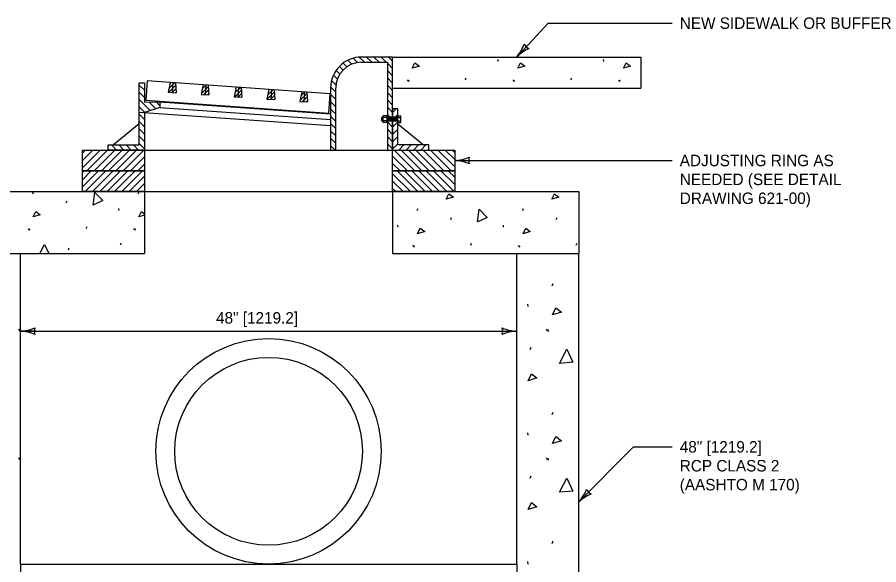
# Model space of a CAD drawing. Extents: x 49991.4 to 50057, y 49987.6 to 50011.4.
# Drawn here: x 50001.401 to 50005.915, y 49990.219 to 49993.085 of the extents above; entities that cross this region are included whole.
import ezdxf

# ---------------------------------------------------------------- set-up
doc = ezdxf.new("R2010")
doc.units = 0
for name, color, linetype in [('Level 1', 7, 'Continuous'), ('Level 2', 7, 'Continuous'), ('Level 3', 7, 'Continuous'), ('Level 4', 7, 'Continuous')]:
    doc.layers.add(name, color=color, linetype=linetype)

msp = doc.modelspace()

# ---------------------------------------------------------------- linework, layer by layer
at = {"layer": 'Level 1'}
for p, q in [((50003.1932, 49992.8766), (50003.2199, 49992.85)), ((50003.2311, 49992.8771), (50003.2582, 49992.85)), ((50003.2694, 49992.8771), (50003.2965, 49992.85)), ((50003.3077, 49992.8771), (50003.3348, 49992.85)), ((50003.346, 49992.8771), (50003.3679, 49992.8552)), ((50003.3679, 49992.8771), (50004.6679, 49992.8771)), ((50004.6679, 49992.8771), (50004.6679, 49992.7146)), ((50003.0889, 49992.8278), (50003.108, 49992.8087)), ((50003.1093, 49992.8456), (50003.1288, 49992.8262)), ((50003.1331, 49992.8601), (50003.1536, 49992.8397)), ((50003.1607, 49992.8708), (50003.1834, 49992.8482)), ((50003.3408, 49992.844), (50003.3679, 49992.8169)), ((50003.9187, 49992.8632), (50003.9198, 49992.8528)), ((50004.4717, 49992.8632), (50004.4728, 49992.8528)), ((50003.0716, 49992.8068), (50003.0911, 49992.7872)), ((50003.3408, 49992.8057), (50003.3679, 49992.7786)), ((50002.203, 49992.7433), (50002.1927, 49992.6931)), ((50002.1969, 49992.7135), (50002.2252, 49992.7418)), ((50002.2018, 49992.7375), (50002.2073, 49992.743)), ((50002.2165, 49992.7424), (50002.213, 49992.6917)), ((50002.23, 49992.7414), (50002.2333, 49992.6903)), ((50003.0478, 49992.754), (50003.071, 49992.7308)), ((50003.0577, 49992.7824), (50003.0784, 49992.7616)), ((50003.3408, 49992.7674), (50003.3679, 49992.7403)), ((50003.4445, 49992.7583), (50003.4491, 49992.7513)), ((50003.4491, 49992.7556), (50003.4537, 49992.7487)), ((50003.7493, 49992.7583), (50003.7539, 49992.7687)), ((50003.9975, 49992.7583), (50004.0021, 49992.7513)), ((50004.0021, 49992.7556), (50004.0067, 49992.7487)), ((50004.3022, 49992.7583), (50004.3069, 49992.7687)), ((50004.5505, 49992.7583), (50004.5551, 49992.7513)), ((50004.5551, 49992.7556), (50004.5597, 49992.7487)), ((50002.0408, 49992.7305), (50002.0679, 49992.7034)), ((50002.0408, 49992.6922), (50002.0679, 49992.6651)), ((50002.1927, 49992.6931), (50002.2333, 49992.6903)), ((50002.1955, 49992.6929), (50002.2309, 49992.7283)), ((50002.2134, 49992.6917), (50002.232, 49992.7103)), ((50002.2313, 49992.6904), (50002.2331, 49992.6922)), ((50002.3753, 49992.7313), (50002.365, 49992.6811)), ((50002.3659, 49992.6856), (50002.4027, 49992.7225)), ((50002.3708, 49992.7097), (50002.3913, 49992.7302)), ((50002.3795, 49992.6801), (50002.4038, 49992.7044)), ((50002.3888, 49992.7303), (50002.3852, 49992.6797)), ((50002.4023, 49992.7294), (50002.4055, 49992.6783)), ((50002.5475, 49992.7192), (50002.5372, 49992.6691)), ((50002.5405, 49992.6688), (50002.5754, 49992.7037)), ((50002.5412, 49992.6887), (50002.5702, 49992.7177)), ((50002.5462, 49992.7128), (50002.5523, 49992.7189)), ((50002.561, 49992.7183), (50002.5575, 49992.6676)), ((50002.5745, 49992.7173), (50002.5777, 49992.6662)), ((50002.7197, 49992.7072), (50002.7094, 49992.657)), ((50002.7112, 49992.6569), (50002.7475, 49992.6932)), ((50002.7139, 49992.6787), (50002.7409, 49992.7057)), ((50002.7188, 49992.7028), (50002.723, 49992.707)), ((50002.7332, 49992.7062), (50002.7297, 49992.6556)), ((50002.7468, 49992.7053), (50002.75, 49992.6542)), ((50002.892, 49992.6951), (50002.8817, 49992.645)), ((50002.8875, 49992.6735), (50002.908, 49992.694)), ((50002.9055, 49992.6942), (50002.9019, 49992.6435)), ((50002.919, 49992.6933), (50002.9222, 49992.6421)), ((50003.043, 49992.7204), (50003.07, 49992.6935)), ((50003.3408, 49992.7291), (50003.3679, 49992.702)), ((50003.3679, 49992.7146), (50004.6679, 49992.7146)), ((50002.0408, 49992.6539), (50002.0985, 49992.5962)), ((50002.365, 49992.6811), (50002.4055, 49992.6783)), ((50002.3974, 49992.6788), (50002.405, 49992.6864)), ((50002.5372, 49992.6691), (50002.5777, 49992.6662)), ((50002.5584, 49992.6676), (50002.5765, 49992.6857)), ((50002.5763, 49992.6663), (50002.5776, 49992.6677)), ((50002.7094, 49992.657), (50002.75, 49992.6542)), ((50002.7291, 49992.6556), (50002.7486, 49992.6752)), ((50002.747, 49992.6544), (50002.7498, 49992.6572)), ((50002.8826, 49992.6494), (50002.9194, 49992.6863)), ((50002.8962, 49992.6439), (50002.9206, 49992.6683)), ((50002.9141, 49992.6427), (50002.9217, 49992.6502)), ((50003.0429, 49992.6823), (50003.07, 49992.6552)), ((50003.3408, 49992.6908), (50003.3679, 49992.6637)), ((50003.3408, 49992.6524), (50003.3679, 49992.6254)), ((50002.0408, 49992.6156), (50002.0698, 49992.5866)), ((50002.0925, 49992.6405), (50002.1273, 49992.6057)), ((50002.1301, 49992.6412), (50002.1492, 49992.6221)), ((50002.1492, 49992.6416), (50002.1492, 49992.6416)), ((50002.1492, 49992.6416), (50003.0429, 49992.5791)), ((50002.1492, 49992.613), (50003.0429, 49992.5505)), ((50002.2152, 49992.6083), (50002.2152, 49992.6083)), ((50002.8817, 49992.645), (50002.9222, 49992.6421)), ((50003.0429, 49992.644), (50003.07, 49992.6169)), ((50003.0429, 49992.6057), (50003.07, 49992.5786)), ((50003.3408, 49992.6141), (50003.3679, 49992.5871)), ((50003.3679, 49992.587), (50003.3872, 49992.6063)), ((50002.0408, 49992.5878), (50003.0429, 49992.5178)), ((50002.0408, 49992.5773), (50002.0679, 49992.5502)), ((50003.0429, 49992.5673), (50003.07, 49992.5403)), ((50003.31, 49992.5589), (50003.3134, 49992.5622)), ((50003.31, 49992.5589), (50003.31, 49992.5453)), ((50003.3117, 49992.5589), (50003.3117, 49992.5453)), ((50003.3134, 49992.5622), (50003.3134, 49992.5419)), ((50003.3168, 49992.5622), (50003.3134, 49992.5622)), ((50003.3151, 49992.5589), (50003.3151, 49992.5453)), ((50003.3168, 49992.5389), (50003.3168, 49992.5653)), ((50003.3168, 49992.5622), (50003.3168, 49992.5419)), ((50003.34, 49992.5697), (50003.3191, 49992.5697)), ((50003.34, 49992.5609), (50003.3191, 49992.5609)), ((50003.34, 49992.5345), (50003.34, 49992.5697)), ((50003.3408, 49992.5673), (50003.34, 49992.5673)), ((50003.3408, 49992.5758), (50003.3679, 49992.5488)), ((50003.3408, 49992.5369), (50003.3408, 49992.5673)), ((50003.395, 49992.5622), (50003.3408, 49992.5622)), ((50003.3422, 49992.5589), (50003.3422, 49992.5453)), ((50003.3438, 49992.5622), (50003.3438, 49992.5419)), ((50003.3455, 49992.5589), (50003.3455, 49992.5453)), ((50003.3472, 49992.5622), (50003.3472, 49992.5419)), ((50003.3489, 49992.5589), (50003.3489, 49992.5453)), ((50003.3506, 49992.5622), (50003.3506, 49992.5419)), ((50003.3523, 49992.5589), (50003.3523, 49992.5453)), ((50003.354, 49992.5622), (50003.354, 49992.5419)), ((50003.3557, 49992.5589), (50003.3557, 49992.5453)), ((50003.3574, 49992.5622), (50003.3574, 49992.5419)), ((50003.3591, 49992.5589), (50003.3591, 49992.5453)), ((50003.3608, 49992.5622), (50003.3608, 49992.5419)), ((50003.3625, 49992.5589), (50003.3625, 49992.5453)), ((50003.3642, 49992.5622), (50003.3642, 49992.5419)), ((50003.3658, 49992.5589), (50003.3658, 49992.5453)), ((50003.3675, 49992.5622), (50003.3675, 49992.5419)), ((50003.3679, 49992.5487), (50003.395, 49992.5758)), ((50003.3692, 49992.5589), (50003.3692, 49992.5453)), ((50003.3709, 49992.5622), (50003.3709, 49992.5419)), ((50003.3726, 49992.5589), (50003.3726, 49992.5453)), ((50003.3743, 49992.5622), (50003.3743, 49992.5419)), ((50003.376, 49992.5589), (50003.376, 49992.5453)), ((50003.3777, 49992.5622), (50003.3777, 49992.5419)), ((50003.3794, 49992.5589), (50003.3794, 49992.5453)), ((50003.3811, 49992.5622), (50003.3811, 49992.5419)), ((50003.3828, 49992.5589), (50003.3828, 49992.5453)), ((50003.3845, 49992.5622), (50003.3845, 49992.5419)), ((50003.3862, 49992.5589), (50003.3862, 49992.5453)), ((50003.3879, 49992.5622), (50003.3879, 49992.5419)), ((50003.3895, 49992.5589), (50003.3895, 49992.5453)), ((50003.3912, 49992.5622), (50003.3912, 49992.5419)), ((50003.3929, 49992.5589), (50003.3929, 49992.5453)), ((50003.395, 49992.5369), (50003.395, 49992.5673)), ((50003.395, 49992.5673), (50003.3958, 49992.5673)), ((50003.3958, 49992.5697), (50003.4086, 49992.5697)), ((50003.3958, 49992.5345), (50003.3958, 49992.5697)), ((50003.3958, 49992.5609), (50003.4086, 49992.5609)), ((50003.411, 49992.5389), (50003.411, 49992.5653)), ((50002.0408, 49992.5277), (50001.9054, 49992.4167)), ((50002.0408, 49992.539), (50002.0679, 49992.5119)), ((50003.0429, 49992.529), (50003.07, 49992.502)), ((50003.31, 49992.5453), (50003.3134, 49992.5419)), ((50003.3168, 49992.5419), (50003.3134, 49992.5419)), ((50003.34, 49992.5433), (50003.3191, 49992.5433)), ((50003.34, 49992.5345), (50003.3191, 49992.5345)), ((50003.3408, 49992.5369), (50003.34, 49992.5369)), ((50003.395, 49992.5419), (50003.3408, 49992.5419)), ((50003.3408, 49992.5375), (50003.3679, 49992.5105)), ((50003.3679, 49992.5104), (50003.395, 49992.5375)), ((50003.395, 49992.5369), (50003.3958, 49992.5369)), ((50003.395, 49992.5277), (50003.395, 49992.5277)), ((50003.395, 49992.5277), (50003.5304, 49992.4167)), ((50003.3958, 49992.5433), (50003.4086, 49992.5433)), ((50003.3958, 49992.5345), (50003.4086, 49992.5345)), ((50002.0408, 49992.5007), (50002.0679, 49992.4736)), ((50003.0429, 49992.4907), (50003.07, 49992.4637)), ((50003.3408, 49992.4992), (50003.3679, 49992.4722)), ((50003.3679, 49992.4721), (50003.395, 49992.4992)), ((50002.0408, 49992.4624), (50002.0679, 49992.4353)), ((50002.0408, 49992.4241), (50002.0679, 49992.397)), ((50003.0429, 49992.4524), (50003.07, 49992.4254)), ((50003.3408, 49992.4609), (50003.3679, 49992.4339)), ((50003.3408, 49992.4226), (50003.3679, 49992.3956)), ((50003.3679, 49992.4338), (50003.395, 49992.4609)), ((50003.3679, 49992.3955), (50003.395, 49992.4226)), ((50001.7429, 49992.2971), (50001.8354, 49992.3896)), ((50001.7429, 49992.3354), (50001.7971, 49992.3896)), ((50001.7429, 49992.3737), (50001.7588, 49992.3896)), ((50001.7653, 49992.2813), (50001.8737, 49992.3896)), ((50001.8036, 49992.2813), (50001.912, 49992.3896)), ((50001.8419, 49992.2813), (50001.9503, 49992.3896)), ((50001.8783, 49992.3951), (50001.8838, 49992.3896)), ((50001.8783, 49992.3951), (50001.8838, 49992.3896)), ((50001.8802, 49992.2813), (50001.9886, 49992.3896)), ((50001.895, 49992.4167), (50001.9221, 49992.3896)), ((50001.9054, 49992.4167), (50001.9054, 49992.4167)), ((50001.9185, 49992.2813), (50002.0269, 49992.3896)), ((50001.9333, 49992.4167), (50001.9604, 49992.3896)), ((50001.9569, 49992.2813), (50002.0652, 49992.3896)), ((50001.9716, 49992.4167), (50001.9987, 49992.3896)), ((50002.0099, 49992.4167), (50002.037, 49992.3896)), ((50002.0679, 49992.3896), (50003.3679, 49992.3896)), ((50003.0429, 49992.4141), (50003.0675, 49992.3896)), ((50003.3751, 49992.3896), (50003.4834, 49992.2813)), ((50003.4003, 49992.3896), (50003.4274, 49992.4167)), ((50003.4134, 49992.3896), (50003.5217, 49992.2813)), ((50003.4386, 49992.3896), (50003.4657, 49992.4167)), ((50003.4517, 49992.3896), (50003.56, 49992.2813)), ((50003.4769, 49992.3896), (50003.504, 49992.4167)), ((50003.49, 49992.3896), (50003.5983, 49992.2813)), ((50003.5152, 49992.3896), (50003.5423, 49992.4167)), ((50003.5283, 49992.3896), (50003.6366, 49992.2813)), ((50003.5304, 49992.4167), (50003.5304, 49992.4167)), ((50003.5535, 49992.3896), (50003.5575, 49992.3935)), ((50003.5535, 49992.3896), (50003.5575, 49992.3935)), ((50003.5666, 49992.3896), (50003.6749, 49992.2813)), ((50003.6049, 49992.3896), (50003.6929, 49992.3016)), ((50003.6432, 49992.3896), (50003.6929, 49992.3399)), ((50003.6815, 49992.3896), (50003.6929, 49992.3782)), ((50001.9952, 49992.2813), (50002.0679, 49992.354)), ((50003.3679, 49992.3584), (50003.4451, 49992.2813)), ((50002.0335, 49992.2813), (50002.0679, 49992.3157)), ((50003.3679, 49992.3201), (50003.4068, 49992.2813)), ((50001.7429, 49992.1966), (50001.8276, 49992.2813)), ((50001.7429, 49992.2349), (50001.7893, 49992.2813)), ((50001.7429, 49992.2732), (50001.751, 49992.2813)), ((50001.7576, 49992.1729), (50001.8659, 49992.2813)), ((50001.7959, 49992.1729), (50001.9042, 49992.2813)), ((50001.8342, 49992.1729), (50001.9425, 49992.2813)), ((50001.8725, 49992.1729), (50001.9808, 49992.2813)), ((50001.9108, 49992.1729), (50002.0191, 49992.2813)), ((50001.9491, 49992.1729), (50002.0574, 49992.2813)), ((50001.9874, 49992.1729), (50002.0679, 49992.2535)), ((50003.3679, 49992.2818), (50003.3685, 49992.2813)), ((50003.3679, 49992.2661), (50003.4611, 49992.1729)), ((50003.3911, 49992.2813), (50003.4994, 49992.1729)), ((50003.4294, 49992.2813), (50003.5377, 49992.1729)), ((50003.4677, 49992.2813), (50003.576, 49992.1729)), ((50003.506, 49992.2813), (50003.6143, 49992.1729)), ((50003.5443, 49992.2813), (50003.6526, 49992.1729)), ((50003.5826, 49992.2813), (50003.6909, 49992.1729)), ((50003.6209, 49992.2813), (50003.6929, 49992.2092)), ((50003.6592, 49992.2813), (50003.6929, 49992.2475)), ((50002.0257, 49992.1729), (50002.0679, 49992.2152)), ((50003.3679, 49992.2278), (50003.4228, 49992.1729)), ((50001.0929, 49992.1729), (50002.0679, 49992.1729)), ((50001.4825, 49992.1611), (50001.4871, 49992.1715)), ((50002.0355, 49992.1611), (50002.0401, 49992.1715)), ((50002.064, 49992.1729), (50002.0679, 49992.1769)), ((50002.0679, 49992.1729), (50002.0679, 49991.8479)), ((50002.0679, 49992.1729), (50003.3679, 49992.1729)), ((50003.3679, 49992.1895), (50003.3845, 49992.1729)), ((50003.3679, 49992.1729), (50004.3429, 49992.1729)), ((50003.3679, 49992.1729), (50003.3679, 49991.8479)), ((50004.3429, 49992.1729), (50004.3429, 49991.8479)), ((50001.658, 49992.1138), (50001.6626, 49992.1242)), ((50001.9324, 49992.0848), (50001.9336, 49992.0744)), ((50003.4966, 49992.0732), (50003.5012, 49992.0836)), ((50004.0496, 49992.0732), (50004.0542, 49992.0836)), ((50002.0679, 49992.0493), (50002.0378, 49992.0399)), ((50003.6721, 49992.0259), (50003.6767, 49992.0362)), ((50004.225, 49992.0259), (50004.2297, 49992.0362)), ((50001.4582, 49991.9799), (50001.4628, 49991.973)), ((50001.4628, 49991.9773), (50001.4675, 49991.9703)), ((50001.763, 49991.9799), (50001.7676, 49991.9903)), ((50002.0112, 49991.9799), (50002.0158, 49991.973)), ((50002.0158, 49991.9773), (50002.0205, 49991.9703)), ((50003.3935, 49991.9969), (50003.3947, 49991.9865)), ((50003.9465, 49991.9969), (50003.9477, 49991.9865)), ((50001.9431, 49991.8943), (50001.9477, 49991.9047)), ((50003.4723, 49991.8919), (50003.4769, 49991.885)), ((50003.4769, 49991.8893), (50003.4816, 49991.8824)), ((50003.7771, 49991.8919), (50003.7817, 49991.9023)), ((50004.0253, 49991.8919), (50004.0299, 49991.885)), ((50004.0299, 49991.8893), (50004.0346, 49991.8824)), ((50004.3301, 49991.8919), (50004.3347, 49991.9023)), ((50001.0929, 49991.8479), (50002.0679, 49991.8479)), ((50001.4179, 49990.2229), (50001.4179, 49991.8479)), ((50001.6695, 49991.8678), (50001.6741, 49991.8782)), ((50003.3679, 49991.8479), (50004.3429, 49991.8479)), ((50004.0179, 49990.2229), (50004.0179, 49991.8479)), ((50004.3429, 49989.8979), (50004.3429, 49991.8479)), ((50004.2031, 49991.6791), (50004.2089, 49991.6921)), ((50004.0743, 49991.5837), (50004.0758, 49991.5707)), ((50001.4079, 49991.4525), (50001.4137, 49991.4439)), ((50001.4137, 49991.4493), (50001.4179, 49991.4429)), ((50004.1728, 49991.4525), (50004.1786, 49991.4439)), ((50004.1786, 49991.4493), (50004.1844, 49991.4406)), ((50004.0877, 49991.3456), (50004.0934, 49991.3586)), ((50004.2031, 49991.005), (50004.2089, 49991.018)), ((50004.0743, 49990.9096), (50004.0758, 49990.8966)), ((50001.4079, 49990.7785), (50001.4137, 49990.7698)), ((50001.4137, 49990.7752), (50001.4179, 49990.7688)), ((50004.1728, 49990.7785), (50004.1786, 49990.7698)), ((50004.1786, 49990.7752), (50004.1844, 49990.7665)), ((50004.0877, 49990.6715), (50004.0934, 49990.6845)), ((50004.2031, 49990.3309), (50004.2089, 49990.3439)), ((50001.4179, 49990.2229), (50004.0179, 49990.2229)), ((50001.4179, 49990.2229), (50004.0179, 49990.2229)), ((50002.002, 49990.2229), (50002.0021, 49990.2226)), ((50002.6933, 49990.2229), (50002.6933, 49990.2226)), ((50003.3845, 49990.2229), (50003.3845, 49990.2226)), ((50004.0743, 49990.2355), (50004.0758, 49990.2226))]:
    msp.add_line(p, q, dxfattribs=at)
for points in [[(50003.2054, 49992.85), (50003.3408, 49992.85), (50003.3408, 49992.3896), (50003.3679, 49992.3896), (50003.3679, 49992.8771), (50003.2054, 49992.8771)], [(50003.471, 49992.8183), (50003.4849, 49992.8472), (50003.508, 49992.8298), (50003.471, 49992.8183)], [(50004.024, 49992.8183), (50004.0379, 49992.8472), (50004.061, 49992.8298), (50004.024, 49992.8183)], [(50004.577, 49992.8183), (50004.5909, 49992.8472), (50004.614, 49992.8298), (50004.577, 49992.8183)], [(50003.0429, 49992.7146), (50003.0429, 49992.3896), (50003.07, 49992.3896), (50003.07, 49992.7146)], [(50001.7984, 49992.1019), (50001.8076, 49992.1678), (50001.8489, 49992.1252), (50001.7995, 49992.1023)], [(50003.6492, 49992.1327), (50003.663, 49992.1615), (50003.6861, 49992.1442), (50003.6492, 49992.1327)], [(50004.2022, 49992.1327), (50004.216, 49992.1615), (50004.2391, 49992.1442), (50004.2022, 49992.1327)], [(50001.4848, 49992.0399), (50001.4986, 49992.0688), (50001.5217, 49992.0515), (50001.4848, 49992.0399)], [(50002.0378, 49992.0399), (50002.0516, 49992.0688), (50002.0679, 49992.0566)], [(50003.8125, 49992.0139), (50003.8217, 49992.0799), (50003.863, 49992.0372), (50003.8136, 49992.0143)], [(50003.4989, 49991.952), (50003.5127, 49991.9808), (50003.5358, 49991.9635), (50003.4989, 49991.952)], [(50004.0519, 49991.952), (50004.0657, 49991.9808), (50004.0888, 49991.9635), (50004.0519, 49991.952)], [(50001.5196, 49991.8479), (50001.5448, 49991.8955), (50001.5661, 49991.8479)], [(50004.206, 49991.5276), (50004.2233, 49991.5637), (50004.2522, 49991.542), (50004.206, 49991.5276)], [(50004.2421, 49991.2734), (50004.2811, 49991.347), (50004.3114, 49991.2792), (50004.2435, 49991.2734)], [(50004.0776, 49991.1825), (50004.0949, 49991.2186), (50004.1237, 49991.1969), (50004.0776, 49991.1825)], [(50004.206, 49990.8535), (50004.2233, 49990.8896), (50004.2522, 49990.8679), (50004.206, 49990.8535)], [(50004.2421, 49990.5994), (50004.2811, 49990.6729), (50004.3114, 49990.6051), (50004.2435, 49990.5994)], [(50004.0776, 49990.5084), (50004.0949, 49990.5445), (50004.1237, 49990.5229), (50004.0776, 49990.5084)]]:
    msp.add_lwpolyline(points, dxfattribs=at)
for points in [[(50002.0679, 49992.5859), (50002.0679, 49992.3896), (50001.8783, 49992.3896), (50001.8783, 49992.4167), (50002.0408, 49992.4167), (50002.0408, 49992.7417), (50002.0679, 49992.7417), (50002.0679, 49992.6401), (50002.1492, 49992.6416), (50002.1492, 49992.613)], [(50003.0406, 49992.6848), (50002.0814, 49992.7518), (50002.0744, 49992.6505), (50003.0335, 49992.5834)], [(50003.395, 49992.4167), (50003.395, 49992.6063), (50003.3679, 49992.6063), (50003.3679, 49992.3896), (50003.5575, 49992.3896), (50003.5575, 49992.4167)], [(50001.7429, 49992.3896), (50002.0679, 49992.3896), (50002.0679, 49992.2813), (50001.7429, 49992.2813)], [(50003.3679, 49992.3896), (50003.6929, 49992.3896), (50003.6929, 49992.2813), (50003.3679, 49992.2813)], [(50001.7429, 49992.2813), (50002.0679, 49992.2813), (50002.0679, 49992.1729), (50001.7429, 49992.1729)], [(50003.3679, 49992.2813), (50003.6929, 49992.2813), (50003.6929, 49992.1729), (50003.3679, 49992.1729)]]:
    msp.add_lwpolyline(points, close=True, dxfattribs=at)
for radius in [0.5901, 0.4918]:
    msp.add_circle((50002.7179, 49990.813), radius, dxfattribs=at)
for centre, radius, start, end in [((50003.2054, 49992.7146), 0.1625, 90, 180), ((50003.2054, 49992.7146), 0.1354, 90, 180), ((50003.322, 49992.5653), 0.00528, 123.6844, 236.3156), ((50003.3343, 49992.5521), 0.0176, 150.0207, 209.9793), ((50003.4057, 49992.5653), 0.00528, 303.6844, 56.3156), ((50003.3934, 49992.5521), 0.0176, 330.0207, 29.9793), ((50003.322, 49992.5389), 0.00528, 123.6376, 236.3624), ((50003.4057, 49992.5389), 0.00528, 303.6376, 56.3624)]:
    msp.add_arc(centre, radius, start, end, dxfattribs=at)
at = {"layer": 'Level 3'}
for p, q in [((50004.0179, 49992.8771), (50004.1829, 49993.0544)), ((50004.1829, 49993.0544), (50004.8321, 49993.0544)), ((50003.6929, 49992.3354), (50004.8321, 49992.3354)), ((50001.4959, 49991.4417), (50001.4179, 49991.4417)), ((50001.4179, 49991.4417), (50004.0179, 49991.4417)), ((50004.3429, 49990.5479), (50004.6303, 49990.8363)), ((50004.6303, 49990.8363), (50004.8321, 49990.8363))]:
    msp.add_line(p, q, dxfattribs=at)
for centre, radius, start, end in [((50003.8397, 49993.0272), 0.233, 319.8832, 339.1331), ((50004.1743, 49992.719), 0.2223, 114.5119, 134.6954), ((50004.1053, 49992.9709), 0.0548, 209.1947, 244.9171), ((50003.6814, 49992.5681), 0.233, 272.8273, 292.0772), ((50003.6837, 49992.1133), 0.2223, 67.456, 87.6395), ((50003.8211, 49992.3354), 0.0548, 162.1388, 197.8612), ((50001.4064, 49991.6744), 0.233, 272.8273, 292.0772), ((50001.4087, 49991.2195), 0.2223, 67.456, 87.6395), ((50001.5461, 49991.4417), 0.0548, 162.1388, 197.8612), ((50004.0271, 49991.6638), 0.2223, 247.456, 267.6395), ((50003.8897, 49991.4417), 0.0548, 342.1388, 17.8612), ((50004.0294, 49991.209), 0.233, 92.8273, 112.0772), ((50004.17, 49990.704), 0.233, 317.9284, 337.1783), ((50004.4938, 49990.3846), 0.2223, 112.5571, 132.7406), ((50004.4334, 49990.6387), 0.0548, 207.2399, 242.9623)]:
    msp.add_arc(centre, radius, start, end, dxfattribs=at)
at = {"layer": 'Level 4'}
for p, q in [((50001.4179, 49990.2229), (50001.4179, 49989.5729)), ((50004.0179, 49990.2229), (50004.0179, 49989.5729))]:
    msp.add_line(p, q, dxfattribs=at)

# ---------------------------------------------------------------- texts
at = {"layer": 'Level 2'}
for s, p in [('NEW SIDEWALK OR BUFFER', (50004.8721, 49993.0244)), ('ADJUSTING RING AS', (50004.8721, 49992.3054)), ('NEEDED (SEE DETAIL', (50004.8721, 49992.2065)), ('DRAWING 621-00)', (50004.8721, 49992.1076)), ('48" [1219.2]', (50002.4428, 49991.4817)), ('48" [1219.2] ', (50004.8721, 49990.8063)), ('RCP CLASS 2', (50004.8721, 49990.7074)), ('(AASHTO M 170)', (50004.8721, 49990.6084))]:
    msp.add_text(s, height=0.06, dxfattribs=at).set_placement(p)

doc.saveas('drawing.dxf')
